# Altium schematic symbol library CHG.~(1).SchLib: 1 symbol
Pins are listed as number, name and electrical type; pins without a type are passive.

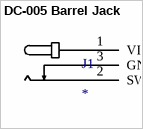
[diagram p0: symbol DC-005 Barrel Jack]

## DC-005 Barrel Jack
designator J1
Barrel Jack to simplify PCB complexity
pins: 1 VIN, 2 SW, 3 GND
